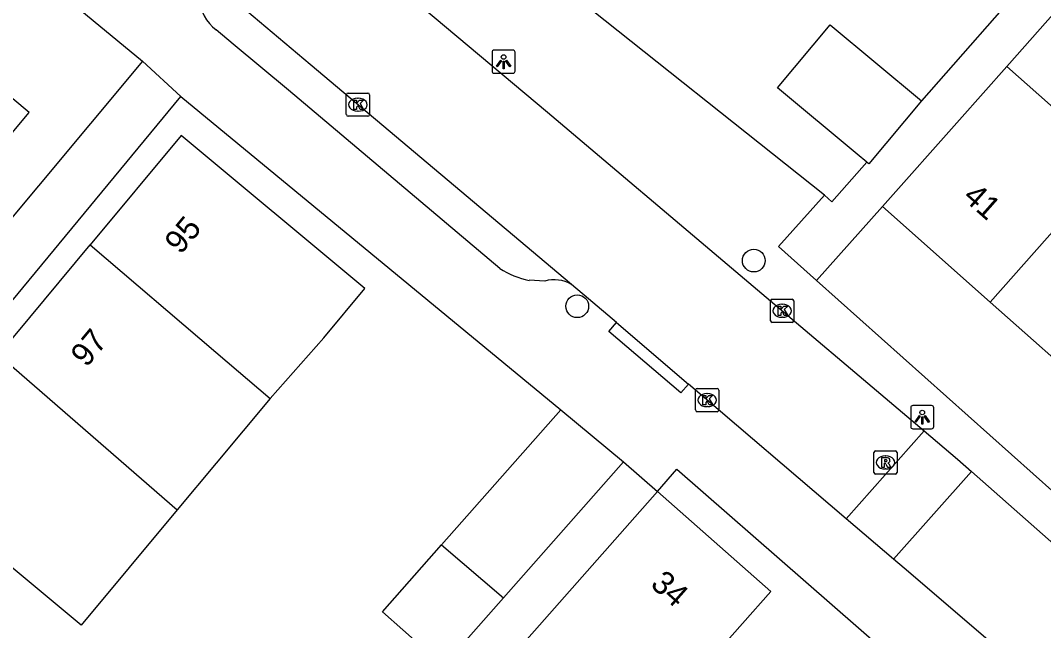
# Model space of a CAD drawing. Extents: x 162532 to 163264, y 381233 to 382042.
# Drawn here: x 162910.58 to 162954.65, y 381538.72 to 381564.99 of the extents above; entities that cross this region are included whole.
import ezdxf

# ---------------------------------------------------------------- set-up
doc = ezdxf.new("R2010")
doc.units = 0
for name, color, linetype in [('IMGEO_Boom', 7, 'Continuous'), ('IMGEO_Kolk', 7, 'Continuous'), ('IMGEO_Lichtpunt', 7, 'Continuous'), ('IMGEO_Pand', 7, 'Continuous'), ('IMGEO_Pand_nummerreeks', 7, 'Continuous'), ('IMGEO_Rijbaan_lokaal_open', 7, 'Continuous'), ('IMGEO_Rioolput', 7, 'Continuous'), ('IMGEO_Voetpad_open', 7, 'Continuous')]:
    doc.layers.add(name, color=color, linetype=linetype)

msp = doc.modelspace()

# ---------------------------------------------------------------- linework, layer by layer
at = {"layer": 'IMGEO_Boom'}
for centre in [(162942.167, 381554.65), (162934.563, 381552.685)]:
    msp.add_circle(centre, 0.489, dxfattribs=at)
at = {"layer": 'IMGEO_Kolk'}
for p, q in [((162924.615, 381560.938), (162924.615, 381561.79)), ((162924.69, 381561.864), (162925.542, 381561.864)), ((162925.616, 381561.79), (162925.616, 381560.938)), ((162925.103, 381561.644), (162925.128, 381561.644)), ((162925.542, 381560.864), (162924.69, 381560.864)), ((162925.126, 381561.084), (162925.101, 381561.084)), ((162942.89, 381552.064), (162942.89, 381552.916)), ((162942.965, 381552.99), (162943.817, 381552.99)), ((162943.891, 381552.916), (162943.891, 381552.064)), ((162943.378, 381552.77), (162943.403, 381552.77)), ((162943.401, 381552.21), (162943.376, 381552.21)), ((162943.817, 381551.99), (162942.965, 381551.99)), ((162939.658, 381548.219), (162939.658, 381549.071)), ((162939.733, 381549.145), (162940.585, 381549.145)), ((162940.146, 381548.925), (162940.171, 381548.925)), ((162940.659, 381549.071), (162940.659, 381548.219)), ((162940.585, 381548.145), (162939.733, 381548.145)), ((162940.169, 381548.365), (162940.144, 381548.365))]:
    msp.add_line(p, q, dxfattribs=at)
for points in [[(162924.615, 381560.938), (162924.615, 381561.79)], [(162924.69, 381561.864), (162925.542, 381561.864)], [(162925.616, 381561.79), (162925.616, 381560.938)], [(162924.936, 381561.564), (162925.059, 381561.564), (162925.059, 381561.413), (162925.189, 381561.564), (162925.353, 381561.564), (162925.207, 381561.413), (162925.36, 381561.164), (162925.208, 381561.164), (162925.123, 381561.328), (162925.059, 381561.261), (162925.059, 381561.164), (162924.936, 381561.164), (162924.936, 381561.564)], [(162925.542, 381560.864), (162924.69, 381560.864)], [(162942.89, 381552.064), (162942.89, 381552.916)], [(162942.965, 381552.99), (162943.817, 381552.99)], [(162943.891, 381552.916), (162943.891, 381552.064)], [(162943.211, 381552.69), (162943.334, 381552.69), (162943.334, 381552.539), (162943.464, 381552.69), (162943.628, 381552.69), (162943.482, 381552.539), (162943.635, 381552.29), (162943.483, 381552.29), (162943.398, 381552.454), (162943.334, 381552.387), (162943.334, 381552.29), (162943.211, 381552.29), (162943.211, 381552.69)], [(162943.817, 381551.99), (162942.965, 381551.99)], [(162939.658, 381548.219), (162939.658, 381549.071)], [(162939.733, 381549.145), (162940.585, 381549.145)], [(162940.659, 381549.071), (162940.659, 381548.219)], [(162939.979, 381548.845), (162940.102, 381548.845), (162940.102, 381548.694), (162940.232, 381548.845), (162940.396, 381548.845), (162940.25, 381548.694), (162940.403, 381548.445), (162940.251, 381548.445), (162940.166, 381548.609), (162940.102, 381548.542), (162940.102, 381548.445), (162939.979, 381548.445), (162939.979, 381548.845)], [(162940.585, 381548.145), (162939.733, 381548.145)]]:
    msp.add_lwpolyline(points, dxfattribs=at)
for centre, start, end in [((162924.692, 381561.788), 91.552, 178.448), ((162924.692, 381561.788), 91.552, 178.448), ((162925.54, 381561.788), 1.552, 88.448), ((162925.54, 381561.788), 1.552, 88.448), ((162924.692, 381560.94), 181.552, 268.448), ((162924.692, 381560.94), 181.552, 268.448), ((162925.54, 381560.94), 271.552, 358.448), ((162925.54, 381560.94), 271.552, 358.448), ((162942.967, 381552.914), 91.552, 178.448), ((162942.967, 381552.914), 91.552, 178.448), ((162943.815, 381552.914), 1.552, 88.448), ((162943.815, 381552.914), 1.552, 88.448), ((162942.967, 381552.066), 181.552, 268.448), ((162942.967, 381552.066), 181.552, 268.448), ((162943.815, 381552.066), 271.552, 358.448), ((162943.815, 381552.066), 271.552, 358.448), ((162939.735, 381549.069), 91.552, 178.448), ((162939.735, 381549.069), 91.552, 178.448), ((162940.583, 381549.069), 1.552, 88.448), ((162940.583, 381549.069), 1.552, 88.448), ((162939.735, 381548.221), 181.552, 268.448), ((162939.735, 381548.221), 181.552, 268.448), ((162940.583, 381548.221), 271.552, 358.448), ((162940.583, 381548.221), 271.552, 358.448)]:
    msp.add_arc(centre, 0.0765, start, end, dxfattribs=at)
for centre, major_axis, ratio, start_param, end_param in [((162925.102, 381561.364), (-0.387, 0.002), 0.722429, 4.712389, 7.853982), ((162925.127, 381561.364), (-0.39, 0.002), 0.717154, 1.570796, 4.712389), ((162943.377, 381552.49), (-0.387, 0.002), 0.722429, 4.712389, 7.853982), ((162943.402, 381552.49), (-0.39, 0.002), 0.717154, 1.570796, 4.712389), ((162940.145, 381548.645), (-0.387, 0.002), 0.722429, 4.712389, 7.853982), ((162940.17, 381548.645), (-0.39, 0.002), 0.717154, 1.570796, 4.712389)]:
    msp.add_ellipse(centre, major_axis=major_axis, ratio=ratio, start_param=start_param, end_param=end_param, dxfattribs=at)
at = {"layer": 'IMGEO_Lichtpunt'}
for p, q in [((162930.891, 381563.619), (162930.891, 381562.812)), ((162930.891, 381563.619), (162930.891, 381562.812)), ((162931.793, 381563.714), (162930.985, 381563.714)), ((162931.793, 381563.714), (162930.985, 381563.714)), ((162931.887, 381562.812), (162931.887, 381563.619)), ((162931.887, 381562.812), (162931.887, 381563.619)), ((162930.985, 381562.718), (162931.793, 381562.718)), ((162930.985, 381562.718), (162931.793, 381562.718)), ((162948.927, 381548.314), (162948.927, 381547.507)), ((162948.927, 381548.314), (162948.927, 381547.507)), ((162949.829, 381548.409), (162949.021, 381548.409)), ((162949.829, 381548.409), (162949.021, 381548.409)), ((162949.923, 381547.507), (162949.923, 381548.314)), ((162949.923, 381547.507), (162949.923, 381548.314)), ((162949.021, 381547.413), (162949.829, 381547.413)), ((162949.021, 381547.413), (162949.829, 381547.413))]:
    msp.add_line(p, q, dxfattribs=at)
for points in [[(162931.265, 381563.283), (162931.304, 381563.255), (162931.116, 381562.993), (162931.078, 381563.02), (162931.265, 381563.283)], [(162931.367, 381563.235), (162931.414, 381563.235), (162931.414, 381562.913), (162931.367, 381562.913), (162931.367, 381563.235)], [(162931.477, 381563.255), (162931.515, 381563.282), (162931.702, 381563.02), (162931.663, 381562.992), (162931.477, 381563.255)], [(162949.301, 381547.978), (162949.34, 381547.95), (162949.152, 381547.688), (162949.114, 381547.715), (162949.301, 381547.978)], [(162949.403, 381547.93), (162949.45, 381547.93), (162949.45, 381547.608), (162949.403, 381547.608), (162949.403, 381547.93)], [(162949.513, 381547.95), (162949.551, 381547.977), (162949.738, 381547.715), (162949.699, 381547.687), (162949.513, 381547.95)]]:
    msp.add_lwpolyline(points, dxfattribs=at)
for centre in [(162931.39, 381563.417), (162949.426, 381548.112)]:
    msp.add_circle(centre, 0.0994, dxfattribs=at)
for centre, start, end in [((162930.985, 381563.619), 90, 180), ((162930.985, 381563.619), 90, 180), ((162931.793, 381563.619), 0, 90), ((162931.793, 381563.619), 0, 90), ((162930.985, 381562.812), 180, 270), ((162930.985, 381562.812), 180, 270), ((162931.793, 381562.812), 270, 0), ((162931.793, 381562.812), 270, 360), ((162949.021, 381548.314), 90, 180), ((162949.021, 381548.314), 90, 180), ((162949.829, 381548.314), 0, 90), ((162949.829, 381548.314), 0, 90), ((162949.021, 381547.507), 180, 270), ((162949.021, 381547.507), 180, 270), ((162949.829, 381547.507), 270, 0), ((162949.829, 381547.507), 270, 360)]:
    msp.add_arc(centre, 0.0946, start, end, dxfattribs=at)
at = {"layer": 'IMGEO_Pand'}
for points in [[(162947.042, 381558.889), (162946.628, 381559.234), (162943.195, 381562.093), (162945.455, 381564.807), (162949.386, 381561.534)], [(162947.718, 381556.975), (162951.035, 381560.718), (162953.069, 381563.013)], [(162953.069, 381563.013), (162957.706, 381558.903)], [(162949.386, 381561.534), (162947.126, 381558.82), (162947.071, 381558.865), (162947.042, 381558.889)], [(162921.328, 381548.716), (162923.645, 381551.329), (162925.412, 381553.449), (162917.506, 381560.039), (162913.576, 381555.324)], [(162957.706, 381558.903), (162952.356, 381552.864)], [(162952.356, 381552.864), (162947.718, 381556.975)], [(162909.627, 381550.587), (162913.576, 381555.324)], [(162913.576, 381555.324), (162918.996, 381550.704), (162921.328, 381548.716)], [(162956.963, 381548.78), (162952.356, 381552.864)], [(162917.328, 381543.916), (162913.187, 381538.948), (162909.215, 381542.259), (162905.362, 381545.47), (162909.627, 381550.587)], [(162909.627, 381550.587), (162917.328, 381543.916)], [(162921.328, 381548.716), (162919.008, 381545.932), (162917.328, 381543.916)], [(162928.721, 381542.414), (162933.857, 381548.227)], [(162933.857, 381548.227), (162936.56, 381545.986)], [(162936.56, 381545.986), (162931.392, 381540.137)], [(162938.022, 381544.713), (162942.899, 381540.407), (162938.024, 381534.891), (162936.119, 381532.736), (162933.593, 381534.968), (162934.309, 381535.778), (162931.961, 381537.853), (162938.022, 381544.713)], [(162931.392, 381540.137), (162928.799, 381537.202), (162926.169, 381539.525), (162928.721, 381542.414)], [(162928.721, 381542.414), (162931.392, 381540.137)]]:
    msp.add_lwpolyline(points, dxfattribs=at)
at = {"layer": 'IMGEO_Rijbaan_lokaal_open'}
for points in [[(162917.851, 381574.024), (162924.31, 381568.58), (162925.474, 381567.598), (162933.285, 381561.036), (162949.507, 381547.316)], [(162934.315, 381553.626), (162923.054, 381563.099), (162917.604, 381567.698)], [(162936.255, 381551.979), (162935.05, 381553.008), (162934.315, 381553.626)], [(162936.255, 381551.979), (162939.349, 381549.337)], [(162946.152, 381543.53), (162939.349, 381549.337)], [(162946.152, 381543.53), (162949.507, 381547.316)], [(162949.507, 381547.316), (162950.943, 381546.101), (162951.542, 381545.572)], [(162948.19, 381541.79), (162951.542, 381545.572)], [(162951.542, 381545.572), (162967.702, 381531.321), (162985.328, 381515.807), (162988.055, 381513.37)], [(162948.19, 381541.79), (162946.152, 381543.53)], [(162954.811, 381536.096), (162953.154, 381537.552), (162948.645, 381541.401), (162948.19, 381541.79)]]:
    msp.add_lwpolyline(points, dxfattribs=at)
at = {"layer": 'IMGEO_Rioolput'}
for p, q in [((162947.339, 381545.534), (162947.339, 381546.386)), ((162947.414, 381546.46), (162948.266, 381546.46)), ((162948.34, 381546.386), (162948.34, 381545.534)), ((162947.827, 381546.24), (162947.852, 381546.24)), ((162948.266, 381545.46), (162947.414, 381545.46)), ((162947.85, 381545.68), (162947.825, 381545.68))]:
    msp.add_line(p, q, dxfattribs=at)
for points in [[(162947.339, 381545.534), (162947.339, 381546.386)], [(162947.414, 381546.46), (162948.266, 381546.46)], [(162948.34, 381546.386), (162948.34, 381545.534)], [(162947.928, 381546.158), (162947.676, 381546.16), (162947.676, 381545.76)], [(162947.676, 381545.76), (162947.8, 381545.76), (162947.8, 381545.922), (162947.811, 381545.922)], [(162947.854, 381546.079), (162947.8, 381546.079), (162947.8, 381545.998)], [(162947.8, 381545.998), (162947.852, 381545.998)], [(162947.858, 381545.893), (162947.929, 381545.76), (162948.069, 381545.76), (162948.004, 381545.886)], [(162948.266, 381545.46), (162947.414, 381545.46)]]:
    msp.add_lwpolyline(points, dxfattribs=at)
for centre, radius, start, end in [((162947.416, 381546.384), 0.0765, 91.552, 178.448), ((162947.416, 381546.384), 0.0765, 91.552, 178.448), ((162948.264, 381546.384), 0.0765, 1.552, 88.448), ((162948.264, 381546.384), 0.0765, 1.552, 88.448), ((162947.81, 381545.869), 0.0533, 26.0293, 88.6989), ((162947.836, 381546.187), 0.19, 274.7715, 282.9687), ((162947.86, 381545.983), 0.0964, 77.0061, 93.1865), ((162947.874, 381546.04), 0.0378, 276.6634, 79.6772), ((162947.927, 381546.048), 0.109, 350.3612, 89.416), ((162947.925, 381546.048), 0.112, 277.5842, 350.9817), ((162947.909, 381545.833), 0.108, 29.5134, 73.7905), ((162947.416, 381545.536), 0.0765, 181.552, 268.448), ((162947.416, 381545.536), 0.0765, 181.552, 268.448), ((162948.264, 381545.536), 0.0765, 271.552, 358.448), ((162948.264, 381545.536), 0.0765, 271.552, 358.448)]:
    msp.add_arc(centre, radius, start, end, dxfattribs=at)
for centre, major_axis, ratio, start_param, end_param in [((162947.826, 381545.96), (-0.387, 0.002), 0.722429, 4.712389, 7.853982), ((162947.851, 381545.96), (-0.39, 0.002), 0.717154, 1.570796, 4.712389)]:
    msp.add_ellipse(centre, major_axis=major_axis, ratio=ratio, start_param=start_param, end_param=end_param, dxfattribs=at)
at = {"layer": 'IMGEO_Voetpad_open'}
for points in [[(162953.069, 381563.013), (162958.137, 381568.744)], [(162954.324, 381567.141), (162949.386, 381561.534)], [(162911.586, 381566.758), (162915.836, 381563.236)], [(162945.207, 381557.469), (162934.089, 381566.322)], [(162931.232, 381554.315), (162922.123, 381561.983), (162919.735, 381563.977), (162919.01, 381564.582)], [(162915.836, 381563.236), (162909.104, 381555.181), (162907.29, 381556.659), (162910.946, 381561.03), (162910.248, 381561.62), (162909.984, 381561.665)], [(162915.836, 381563.236), (162917.487, 381561.716)], [(162902.361, 381543.429), (162917.487, 381561.716)], [(162917.487, 381561.716), (162933.857, 381548.227)], [(162947.042, 381558.889), (162945.523, 381557.187), (162945.207, 381557.469)], [(162945.207, 381557.469), (162943.227, 381555.261), (162944.876, 381553.79)], [(162944.876, 381553.79), (162947.718, 381556.975)], [(162933.165, 381553.768), (162932.492, 381553.802)], [(163002.177, 381508.703), (163000, 381506.279), (162999.351, 381505.556), (162999.264, 381505.633), (162964.471, 381536.308), (162944.876, 381553.79)], [(162939.349, 381549.337), (162939.024, 381548.96), (162935.929, 381551.601), (162936.255, 381551.979)], [(162936.56, 381545.986), (162938.022, 381544.713)], [(162938.022, 381544.713), (162938.851, 381545.67), (162949.96, 381535.97)]]:
    msp.add_lwpolyline(points, dxfattribs=at)
for centre, radius, start, end in [((162920.068, 381566.005), 1.773, 181.1953, 233.3807), ((162933.145, 381557.21), 3.471, 236.5436, 259.1497), ((162933.574, 381552.356), 1.47, 59.7567, 106.165)]:
    msp.add_arc(centre, radius, start, end, dxfattribs=at)

# ---------------------------------------------------------------- texts
at = {"layer": 'IMGEO_Pand_nummerreeks'}
for s, rotation, p in [('41', 318.4465, (162951.125, 381557.323)), ('95', 50.1854, (162917.473, 381554.876)), ('97', 50.1854, (162913.425, 381550.02)), ('34', 318.558, (162937.67, 381540.649))]:
    msp.add_text(s, height=1, rotation=rotation, dxfattribs=at).set_placement(p)

doc.saveas('drawing.dxf')
